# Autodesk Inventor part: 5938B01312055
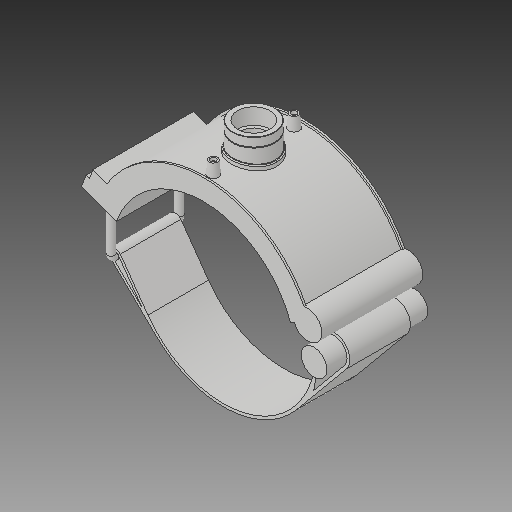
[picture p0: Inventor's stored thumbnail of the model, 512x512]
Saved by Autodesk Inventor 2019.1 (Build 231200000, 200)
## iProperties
Created: 2017-07
Part Number: 5938B01312055
Material: Generic
Description: PLASSON TRANSITION SADDLE 12''IPS x 2"NPT
Document SubType Name: Modeling
Designer: KIM
Density: 1 g/cm^3
Appearance: Default
Author: KIM
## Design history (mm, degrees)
derived "5938B.ipt"
feature "Solid1::5938B.ipt"
tag "TaggingFeature1"
body "Solid1"
other parameters: "d0" = 323.4, "d1" = 388.08, "d2" = 487.045, "d3" = 80.85, "d4" = 176.022, "d5" = 0, "d40" = 201.8016, "d41" = 79.3184, "d43" = 0, "d45" = 0, "d47" = 240.776, "d48" = 73.6528, "d50" = 0, "d78" = 216.04, "d79" = 15, "d80" = 70.4088, "d82" = 5 deg, "d84" = 4, "d85" = 14, "d86" = 0, "d87" = 3, "d88" = 0, "d96" = 395.8416, "d97" = 3.52044, "d98" = 0, "d102" = 1.69968, "d103" = 56.656, "d104" = 28.0416, "d105" = 0, "d106" = 45.3248, "d108" = 0, "d109" = -15.57867, "d111" = 0.5, "d112" = 0.5, "d113" = 0, "d114" = 0.5, "d117" = 0.56656, "d120" = 140 deg, "d121" = 24.228, "d122" = 20 deg, "d123" = 1552.32, "d124" = 232.848, "d126" = 0, "d143" = 333.102, "d145" = 49.75385, "d149" = 4.851, "d150" = 54.72923, "d153" = 176.022, "d154" = 0, "d156" = 194.04, "d157" = 160 deg, "d159" = 12.936, "d161" = 4.851, "d162" = 105.6132, "d163" = 0, "d164" = 161.7, "d167" = 32.34, "d168" = 189.30732, "d170" = 4.851, "d172" = 0, "d173" = 1, "d175" = 161.7, "d176" = 20 deg, "d177" = 22.638, "d178" = 64.68, "d180" = 0, "d183" = 25.872, "d184" = 18.1104, "d185" = 57.20715, "d186" = 57.20715, "d187" = 194.04, "d188" = 19.404, "d189" = 22.638, "d190" = 0, "d191" = 232.848, "d193" = 12.936, "d194" = 6.6297, "d195" = 90 deg, "d197" = 0, "d199" = 0, "d_" = 323.4, "B_" = 194.818, "H_" = 46.736, "L_" = 176.022, "d_t" = 6, "G_" = 56.656, "d148" = 4.851, "d160" = 4.851, "d169" = 4.851, "d192" = 12.936
